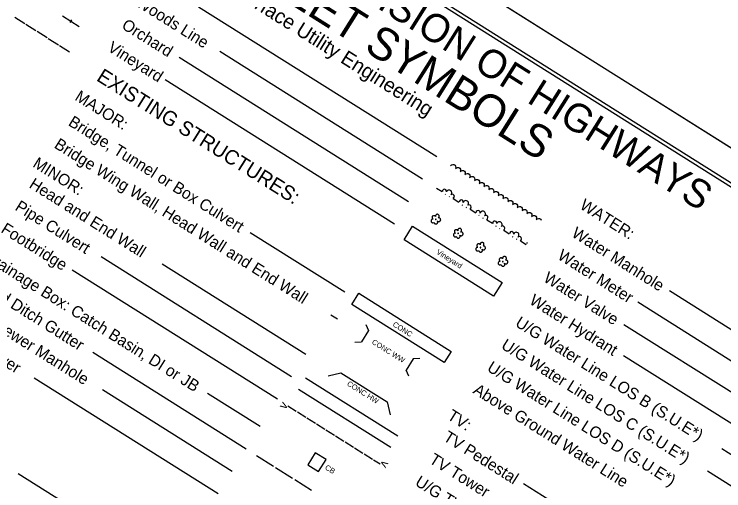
# Model space of a CAD drawing. Extents: x 2337092 to 2349158, y 800756 to 811724.
# Drawn here: x 2344308 to 2347526, y 805793 to 807955 of the extents above; entities that cross this region are included whole.
import ezdxf

# ---------------------------------------------------------------- set-up
doc = ezdxf.new("R2010")
doc.units = 0
for name, color, linetype in [('Sheet Cutting Line CELL', 7, 'Continuous'), ('Sheet Plot Border Inside CELL', 7, 'Continuous'), ('Sheet Plot Border Outside CELL', 7, 'Continuous'), ('Sheet Symbology CELL', 7, 'Continuous')]:
    doc.layers.add(name, color=color, linetype=linetype)

msp = doc.modelspace()

# ---------------------------------------------------------------- linework, layer by layer
at = {"layer": 'Sheet Cutting Line CELL'}
msp.add_line((2349158.5, 806341.3), (2340607.3, 811723.5), dxfattribs=at)
at = {"layer": 'Sheet Plot Border Inside CELL'}
msp.add_lwpolyline([(2337229.4, 806210.3), (2345691.7, 800884), (2349063.9, 806241.7), (2340601.5, 811568)], close=True, dxfattribs=at)
at = {"layer": 'Sheet Plot Border Outside CELL'}
msp.add_lwpolyline([(2337091.6, 806137.8), (2345642.8, 800755.6), (2349158.5, 806341.3), (2340607.3, 811723.5)], close=True, dxfattribs=at)
at = {"layer": 'Sheet Symbology CELL'}
for p, q in [((2346224.2, 807308.1), (2345144.1, 807987.8)), ((2344309.8, 807941.7), (2344355.5, 807912.9)), ((2344526, 807947.4), (2344602.2, 807899.4)), ((2344360.6, 807909.7), (2344406.3, 807881)), ((2344568.1, 807929.7), (2344560.1, 807917)), ((2344411.3, 807877.8), (2344457, 807849)), ((2344462.1, 807845.8), (2344507.8, 807817)), ((2344512.9, 807813.8), (2344558.6, 807785.1)), ((2346160.2, 807206.5), (2345240.5, 807785.4)), ((2346096.1, 807104.1), (2345055.5, 807759.1)), ((2346032.2, 807002.6), (2344991.6, 807657.5)), ((2346287.1, 807268.5), (2346291.6, 807272.3)), ((2346291.6, 807272.3), (2346296.8, 807273.7)), ((2346296.8, 807273.7), (2346302.3, 807273.4)), ((2346302.3, 807273.4), (2346307.1, 807270.4)), ((2346307.1, 807270.4), (2346309.6, 807265.3)), ((2346310.3, 807260.3), (2346308.6, 807255.3)), ((2346308.7, 807254.9), (2346313.2, 807258.8)), ((2346309.6, 807265.3), (2346310.3, 807260.3)), ((2346313.2, 807258.8), (2346318.4, 807260.1)), ((2346318.4, 807260.1), (2346323.9, 807259.9)), ((2346323.9, 807259.9), (2346328.7, 807256.8)), ((2346328.7, 807256.8), (2346331.1, 807251.7)), ((2346331.9, 807246.7), (2346330.2, 807241.7)), ((2346330.2, 807241.3), (2346334.8, 807245.2)), ((2346331.1, 807251.7), (2346331.9, 807246.7)), ((2346334.8, 807245.2), (2346339.9, 807246.6)), ((2346339.9, 807246.6), (2346345.4, 807246.3)), ((2346345.4, 807246.3), (2346350.3, 807243.2)), ((2346350.3, 807243.2), (2346352.7, 807238.1)), ((2346353.4, 807233.1), (2346351.7, 807228.1)), ((2346351.8, 807227.7), (2346356.4, 807231.6)), ((2346352.7, 807238.1), (2346353.4, 807233.1)), ((2346356.4, 807231.6), (2346361.5, 807233)), ((2346361.5, 807233), (2346367, 807232.7)), ((2346367, 807232.7), (2346371.8, 807229.7)), ((2346371.8, 807229.7), (2346374.3, 807224.6)), ((2346374.3, 807224.6), (2346375, 807219.5)), ((2346375, 807219.5), (2346373.3, 807214.6)), ((2346373.4, 807214.1), (2346378, 807218)), ((2346378, 807218), (2346383.1, 807219.4)), ((2346383.1, 807219.4), (2346388.6, 807219.1)), ((2346388.6, 807219.1), (2346393.4, 807216.1)), ((2346393.4, 807216.1), (2346395.9, 807211)), ((2346396.6, 807205.9), (2346394.9, 807201)), ((2346395, 807200.6), (2346399.6, 807204.4)), ((2346395.9, 807211), (2346396.6, 807205.9)), ((2346399.6, 807204.4), (2346404.7, 807205.8)), ((2346404.7, 807205.8), (2346410.2, 807205.5)), ((2346410.2, 807205.5), (2346415, 807202.5)), ((2346415, 807202.5), (2346417.5, 807197.4)), ((2346418.2, 807192.3), (2346416.5, 807187.4)), ((2346417.5, 807197.4), (2346418.2, 807192.3)), ((2346421.1, 807190.8), (2346426.3, 807192.2)), ((2346426.3, 807192.2), (2346431.8, 807191.9)), ((2346223.2, 807166.9), (2346248.6, 807150.9)), ((2346416.6, 807187), (2346421.1, 807190.8)), ((2346431.8, 807191.9), (2346436.6, 807188.9)), ((2346436.6, 807188.9), (2346439, 807183.8)), ((2346439.8, 807178.8), (2346438.1, 807173.8)), ((2346438.2, 807173.4), (2346442.7, 807177.3)), ((2346439, 807183.8), (2346439.8, 807178.8)), ((2346442.7, 807177.3), (2346447.8, 807178.6)), ((2346447.8, 807178.6), (2346453.3, 807178.4)), ((2346453.3, 807178.4), (2346458.2, 807175.3)), ((2346458.2, 807175.3), (2346460.6, 807170.2)), ((2346461.3, 807165.2), (2346459.6, 807160.2)), ((2346459.7, 807159.8), (2346464.3, 807163.7)), ((2346460.6, 807170.2), (2346461.3, 807165.2)), ((2346464.3, 807163.7), (2346469.4, 807165.1)), ((2346469.4, 807165.1), (2346474.9, 807164.8)), ((2346474.9, 807164.8), (2346479.7, 807161.7)), ((2346479.7, 807161.7), (2346482.2, 807156.6)), ((2346261.9, 807139), (2346264.5, 807137.4)), ((2346482.9, 807151.6), (2346481.2, 807146.6)), ((2346481.3, 807146.2), (2346485.9, 807150.1)), ((2346482.2, 807156.6), (2346482.9, 807151.6)), ((2346485.9, 807150.1), (2346491, 807151.5)), ((2346491, 807151.5), (2346496.5, 807151.2)), ((2346496.5, 807151.2), (2346501.3, 807148.2)), ((2346501.3, 807148.2), (2346503.8, 807143.1)), ((2346504.5, 807138), (2346502.8, 807133.1)), ((2346502.9, 807132.6), (2346507.5, 807136.5)), ((2346503.8, 807143.1), (2346504.5, 807138)), ((2346507.5, 807136.5), (2346512.6, 807137.9)), ((2346512.6, 807137.9), (2346518.1, 807137.6)), ((2346518.1, 807137.6), (2346522.9, 807134.6)), ((2346522.9, 807134.6), (2346525.4, 807129.5)), ((2346525.4, 807129.5), (2346526.1, 807124.4)), ((2346279.7, 807127.8), (2346282.2, 807126.2)), ((2346299.3, 807119), (2346324.7, 807103)), ((2346526.1, 807124.4), (2346524.4, 807119.5)), ((2346524.5, 807119.1), (2346529, 807122.9)), ((2346529, 807122.9), (2346534.2, 807124.3)), ((2346534.2, 807124.3), (2346539.7, 807124)), ((2346539.7, 807124), (2346544.5, 807121)), ((2346544.5, 807121), (2346547, 807115.9)), ((2346547.7, 807110.8), (2346546, 807105.9)), ((2346546.1, 807105.5), (2346550.6, 807109.3)), ((2346547, 807115.9), (2346547.7, 807110.8)), ((2346550.6, 807109.3), (2346555.7, 807110.7)), ((2346555.7, 807110.7), (2346561.2, 807110.4)), ((2346561.2, 807110.4), (2346566.1, 807107.4)), ((2346566.1, 807107.4), (2346568.5, 807102.3)), ((2346569.2, 807097.3), (2346567.5, 807092.3)), ((2346567.6, 807091.9), (2346572.2, 807095.8)), ((2346568.5, 807102.3), (2346569.2, 807097.3)), ((2346572.2, 807095.8), (2346577.3, 807097.1)), ((2346577.3, 807097.1), (2346582.8, 807096.9)), ((2346582.8, 807096.9), (2346587.6, 807093.8)), ((2346338.1, 807091), (2346340.6, 807089.4)), ((2346355.9, 807079.8), (2346358.4, 807078.2)), ((2346375.5, 807071), (2346400.9, 807055)), ((2346587.6, 807093.8), (2346590.1, 807088.7)), ((2346590.8, 807083.7), (2346589.1, 807078.7)), ((2346589.2, 807078.3), (2346593.8, 807082.2)), ((2346590.1, 807088.7), (2346590.8, 807083.7)), ((2346593.8, 807082.2), (2346598.9, 807083.6)), ((2346598.9, 807083.6), (2346604.4, 807083.3)), ((2346604.4, 807083.3), (2346609.2, 807080.2)), ((2346609.2, 807080.2), (2346611.7, 807075.1)), ((2346612.4, 807070.1), (2346610.7, 807065.1)), ((2346610.8, 807064.7), (2346615.4, 807068.6)), ((2346611.7, 807075.1), (2346612.4, 807070.1)), ((2346615.4, 807068.6), (2346620.5, 807070)), ((2346620.5, 807070), (2346626, 807069.7)), ((2346626, 807069.7), (2346630.8, 807066.7)), ((2346630.8, 807066.7), (2346633.3, 807061.6)), ((2346414.3, 807043.1), (2346416.8, 807041.5)), ((2346432, 807031.9), (2346434.6, 807030.3)), ((2346634, 807056.5), (2346632.3, 807051.6)), ((2346632.4, 807051.1), (2346636.9, 807055)), ((2346633.3, 807061.6), (2346634, 807056.5)), ((2346636.9, 807055), (2346642.1, 807056.4)), ((2346642.1, 807056.4), (2346647.6, 807056.1)), ((2346647.6, 807056.1), (2346652.4, 807053.1)), ((2346652.4, 807053.1), (2346654.9, 807048)), ((2346655.6, 807042.9), (2346653.9, 807038)), ((2346654, 807037.6), (2346658.5, 807041.4)), ((2346654.9, 807048), (2346655.6, 807042.9)), ((2346658.5, 807041.4), (2346663.6, 807042.8)), ((2346663.6, 807042.8), (2346669.1, 807042.5)), ((2346669.1, 807042.5), (2346674, 807039.5)), ((2346674, 807039.5), (2346676.4, 807034.4)), ((2346676.4, 807034.4), (2346677.2, 807029.3)), ((2346451.7, 807023.1), (2346477.1, 807007.1)), ((2346677.2, 807029.3), (2346675.5, 807024.4)), ((2346675.5, 807024), (2346680.1, 807027.8)), ((2346680.1, 807027.8), (2346685.2, 807029.2)), ((2346685.2, 807029.2), (2346690.7, 807028.9)), ((2346690.7, 807028.9), (2346695.6, 807025.9)), ((2346695.6, 807025.9), (2346698, 807020.8)), ((2346698, 807020.8), (2346698.1, 807020.4)), ((2346490.4, 806995.1), (2346493, 806993.5)), ((2346508.2, 806984), (2346510.8, 806982.4)), ((2346527.8, 806975.1), (2346553.2, 806959.2)), ((2345807.3, 806693.9), (2345378.6, 806963.7)), ((2346566.6, 806947.2), (2346569.1, 806945.6)), ((2346584.4, 806936), (2346586.9, 806934.4)), ((2346604, 806927.2), (2346629.4, 806911.2)), ((2345565.8, 806310.1), (2344701.6, 806854.1)), ((2345629.7, 806411.7), (2344978.2, 806821.7)), ((2345501.9, 806208.6), (2344570.2, 806795)), ((2348104.2, 806180.9), (2347279.6, 806699.9)), ((2348040.3, 806079.3), (2347136.2, 806648.4)), ((2345743.4, 806592.3), (2345773.8, 806573.2)), ((2345914.5, 806520.1), (2345882.5, 806469.3)), ((2345902.8, 806547.7), (2345914.5, 806520.1)), ((2347976.4, 805977.8), (2347072.3, 806546.8)), ((2345852.6, 806467.8), (2345882.5, 806469.3)), ((2345359.9, 805983), (2344664.5, 806420.7)), ((2346117.6, 806392.2), (2346085.7, 806341.4)), ((2346147.6, 806393.6), (2346117.6, 806392.2)), ((2347912.5, 805876.2), (2347070.6, 806406.1)), ((2345731.1, 806315.4), (2345789.7, 806328.7)), ((2345789.7, 806328.7), (2345999.1, 806196.9)), ((2346097.3, 806313.8), (2346085.7, 806341.4)), ((2345232, 805779.8), (2344398.2, 806304.6)), ((2345629, 806305.8), (2346047.9, 806042.1)), ((2345296, 805881.4), (2344708.6, 806251.1)), ((2345423.8, 806084.5), (2345184.1, 806235.4)), ((2345597, 806255), (2346016, 805991.3)), ((2345999.1, 806196.9), (2346012.4, 806138.4)), ((2345549.1, 806178.8), (2345587.2, 806154.9)), ((2345592.3, 806151.7), (2345630.3, 806127.7)), ((2345635.4, 806124.5), (2345673.5, 806100.5)), ((2345678.6, 806097.3), (2345716.7, 806073.4)), ((2345721.7, 806070.2), (2345759.8, 806046.2)), ((2345764.9, 806043), (2345803, 806019)), ((2345808.1, 806015.8), (2345846.2, 805991.9)), ((2345851.2, 805988.7), (2345889.3, 805964.7)), ((2347848.5, 805774.7), (2347516.5, 805983.6)), ((2345407.1, 805953.2), (2345483.3, 805905.3)), ((2345894.4, 805961.5), (2345932.5, 805937.5)), ((2345937.6, 805934.4), (2345968, 805915.2)), ((2345493.4, 805898.9), (2345569.6, 805851)), ((2347784.6, 805673.1), (2347452.6, 805882.1)), ((2345030.2, 805427.7), (2344325.9, 805871)), ((2345579.7, 805844.6), (2345655.9, 805796.6)), ((2347522, 805255.9), (2346618, 805824.9))]:
    msp.add_line(p, q, dxfattribs=at)
for points in [[(2348992.3, 806268.7), (2341375.4, 811062.8), (2338022.8, 805736.2), (2345639.6, 800942.1)], [(2345639.1, 805911.4), (2345687.9, 805880.6), (2345721.9, 805934.7), (2345673.1, 805965.4)]]:
    msp.add_lwpolyline(points, close=True, dxfattribs=at)
for points in [[(2346230.9, 807031.7), (2346232.6, 807032.7), (2346233.8, 807034.1), (2346234.6, 807035.8), (2346235.3, 807037.5), (2346235.3, 807039.2), (2346235.3, 807041), (2346234.7, 807042.8), (2346233.9, 807044.3), (2346232.5, 807046), (2346231.2, 807046.8), (2346229.5, 807047.5), (2346227.7, 807047.9), (2346225.9, 807047.9), (2346224, 807047.7), (2346222.3, 807046.7), (2346221, 807045.7), (2346219.8, 807044.4), (2346218.8, 807042.8), (2346218.1, 807041.2), (2346218.1, 807039.4), (2346218.1, 807037.3), (2346217.3, 807038.8), (2346216, 807040), (2346214.4, 807041), (2346212.8, 807041.3), (2346211.3, 807041.6), (2346209.4, 807041.4), (2346207.7, 807041), (2346206.1, 807040.2), (2346205.1, 807039.1), (2346203.7, 807037.5), (2346203.2, 807036), (2346202.9, 807034.4), (2346203.1, 807032.5), (2346203.2, 807031), (2346204, 807029.5), (2346205, 807027.8), (2346206.2, 807026.7), (2346207.7, 807025.7), (2346206.1, 807026), (2346204.2, 807025.8), (2346202.8, 807025.3), (2346201.3, 807024.1), (2346199.8, 807022.9), (2346199, 807021.6), (2346198.3, 807019.9), (2346198.3, 807018.2), (2346198.3, 807016.4), (2346198.6, 807014.8), (2346199.4, 807013.2), (2346200.4, 807011.9), (2346201.9, 807010.9), (2346203.4, 807010), (2346204.9, 807009.4), (2346206.8, 807009.7), (2346208.5, 807009.6), (2346211.2, 807011.1)], [(2346211.2, 807011.1), (2346213.2, 807007.4), (2346214.4, 807005.9), (2346215.7, 807004.7), (2346217.4, 807004), (2346219, 807003.7), (2346220.7, 807003.7), (2346222.7, 807003.9), (2346224.2, 807004.7), (2346225.5, 807005.7), (2346227, 807006.9), (2346227.7, 807008.5), (2346228.4, 807010.2), (2346228.3, 807012.4), (2346228.2, 807013.9), (2346227.4, 807015.4), (2346226.4, 807017.2), (2346227.7, 807015.9), (2346229.5, 807014.8), (2346231.1, 807014.5), (2346233.1, 807014.3), (2346234.9, 807014.3), (2346236.7, 807014.9), (2346238.4, 807016), (2346239.6, 807017.3), (2346240.8, 807018.7), (2346241.5, 807020.4), (2346242, 807022.2), (2346241.8, 807024.1), (2346241.3, 807026.2), (2346240.5, 807027.8), (2346239.3, 807029.2), (2346237.9, 807030.4), (2346236.4, 807031.4), (2346234.6, 807031.9), (2346232.8, 807031.9), (2346230.9, 807031.7)], [(2346221, 807025.5), (2346220.2, 807026), (2346219.6, 807026.1), (2346218.9, 807026.1), (2346218.4, 807025.4), (2346218.1, 807024.9), (2346218.3, 807024), (2346219.1, 807023.5), (2346219.6, 807023.2), (2346220.4, 807023.4), (2346221.1, 807024), (2346221.2, 807024.7), (2346221, 807025.5)], [(2346114.3, 806993.4), (2346520.5, 806737.7), (2346482.2, 806676.8), (2346076, 806932.5), (2346114.3, 806993.4)], [(2346332.5, 806967.8), (2346334.2, 806968.8), (2346335.4, 806970.2), (2346336.1, 806971.8), (2346336.8, 806973.5), (2346336.9, 806975.3), (2346336.9, 806977), (2346336.3, 806978.8), (2346335.5, 806980.4), (2346334, 806982), (2346332.7, 806982.8), (2346331.1, 806983.5), (2346329.2, 806984), (2346327.5, 806984), (2346325.6, 806983.8), (2346323.8, 806982.8), (2346322.5, 806981.8), (2346321.3, 806980.4), (2346320.4, 806978.9), (2346319.7, 806977.2), (2346319.6, 806975.5), (2346319.7, 806973.3), (2346318.9, 806974.9), (2346317.5, 806976.1), (2346316, 806977.1), (2346314.4, 806977.4), (2346312.8, 806977.6), (2346310.9, 806977.4), (2346309.3, 806977.1), (2346307.7, 806976.3), (2346306.6, 806975.2), (2346305.3, 806973.5), (2346304.7, 806972.1), (2346304.4, 806970.5), (2346304.6, 806968.6), (2346304.8, 806967.1), (2346305.6, 806965.6), (2346306.6, 806963.8), (2346307.7, 806962.8), (2346309.2, 806961.8), (2346307.6, 806962.1), (2346305.7, 806961.9), (2346304.3, 806961.4), (2346302.9, 806960.2), (2346301.4, 806959), (2346300.6, 806957.7), (2346299.9, 806956), (2346299.9, 806954.3), (2346299.8, 806952.5), (2346300.2, 806950.8), (2346301, 806949.3), (2346301.9, 806948), (2346303.5, 806947), (2346305, 806946.1), (2346306.4, 806945.5), (2346308.3, 806945.7), (2346310.1, 806945.7), (2346312.8, 806947.2)], [(2346312.8, 806947.2), (2346314.7, 806943.5), (2346315.9, 806942), (2346317.3, 806940.8), (2346319, 806940.1), (2346320.6, 806939.8), (2346322.3, 806939.8), (2346324.2, 806940), (2346325.8, 806940.8), (2346327.1, 806941.7), (2346328.5, 806942.9), (2346329.3, 806944.6), (2346330, 806946.3), (2346329.9, 806948.5), (2346329.8, 806950), (2346329, 806951.5), (2346327.9, 806953.2), (2346329.3, 806952), (2346331.1, 806950.9), (2346332.7, 806950.6), (2346334.7, 806950.4), (2346336.4, 806950.4), (2346338.2, 806951), (2346340, 806952.1), (2346341.2, 806953.4), (2346342.4, 806954.8), (2346343.1, 806956.5), (2346343.5, 806958.3), (2346343.3, 806960.2), (2346342.9, 806962.3), (2346342.1, 806963.8), (2346340.9, 806965.3), (2346339.5, 806966.5), (2346338, 806967.5), (2346336.1, 806967.9), (2346334.4, 806968), (2346332.5, 806967.8)], [(2346322.6, 806961.6), (2346321.8, 806962.1), (2346321.1, 806962.1), (2346320.5, 806962.2), (2346320, 806961.4), (2346319.7, 806960.9), (2346319.9, 806960.1), (2346320.6, 806959.6), (2346321.1, 806959.3), (2346322, 806959.5), (2346322.7, 806960.1), (2346322.8, 806960.8), (2346322.6, 806961.6)], [(2346434, 806903.8), (2346435.8, 806904.9), (2346437, 806906.2), (2346437.7, 806907.9), (2346438.4, 806909.6), (2346438.4, 806911.4), (2346438.4, 806913.1), (2346437.8, 806914.9), (2346437, 806916.5), (2346435.6, 806918.1), (2346434.3, 806918.9), (2346432.6, 806919.6), (2346430.8, 806920.1), (2346429, 806920.1), (2346427.1, 806919.9), (2346425.4, 806918.8), (2346424.1, 806917.9), (2346422.9, 806916.5), (2346421.9, 806915), (2346421.2, 806913.3), (2346421.2, 806911.6), (2346421.2, 806909.4), (2346420.4, 806911), (2346419.1, 806912.2), (2346417.6, 806913.1), (2346416, 806913.4), (2346414.4, 806913.7), (2346412.5, 806913.5), (2346410.8, 806913.1), (2346409.3, 806912.3), (2346408.2, 806911.2), (2346406.8, 806909.6), (2346406.3, 806908.2), (2346406, 806906.6), (2346406.2, 806904.7), (2346406.3, 806903.2), (2346407.1, 806901.6), (2346408.2, 806899.9), (2346409.3, 806898.9), (2346410.8, 806897.9), (2346409.2, 806898.2), (2346407.3, 806898), (2346405.9, 806897.4), (2346404.4, 806896.2), (2346403, 806895), (2346402.2, 806893.8), (2346401.5, 806892.1), (2346401.4, 806890.3), (2346401.4, 806888.6), (2346401.8, 806886.9), (2346402.6, 806885.4), (2346403.5, 806884.1), (2346405, 806883.1), (2346406.5, 806882.1), (2346408, 806881.6), (2346409.9, 806881.8), (2346411.6, 806881.8), (2346414.3, 806883.3)], [(2346414.3, 806883.3), (2346416.3, 806879.6), (2346417.5, 806878.1), (2346418.8, 806876.9), (2346420.5, 806876.2), (2346422.1, 806875.9), (2346423.9, 806875.9), (2346425.8, 806876.1), (2346427.3, 806876.9), (2346428.6, 806877.8), (2346430.1, 806879), (2346430.8, 806880.7), (2346431.5, 806882.4), (2346431.5, 806884.5), (2346431.3, 806886), (2346430.5, 806887.6), (2346429.5, 806889.3), (2346430.9, 806888.1), (2346432.6, 806887), (2346434.2, 806886.7), (2346436.2, 806886.5), (2346438, 806886.5), (2346439.8, 806887.1), (2346441.5, 806888.1), (2346442.7, 806889.5), (2346443.9, 806890.9), (2346444.6, 806892.5), (2346445.1, 806894.4), (2346444.9, 806896.3), (2346444.4, 806898.4), (2346443.6, 806899.9), (2346442.4, 806901.4), (2346441.1, 806902.6), (2346439.5, 806903.6), (2346437.7, 806904), (2346435.9, 806904.1), (2346434, 806903.8)], [(2346424.1, 806897.7), (2346423.4, 806898.1), (2346422.7, 806898.2), (2346422, 806898.3), (2346421.5, 806897.5), (2346421.2, 806897), (2346421.4, 806896.2), (2346422.2, 806895.7), (2346422.7, 806895.4), (2346423.5, 806895.6), (2346424.2, 806896.2), (2346424.3, 806896.8), (2346424.1, 806897.7)], [(2346535.6, 806839.9), (2346537.3, 806841), (2346538.5, 806842.3), (2346539.2, 806844), (2346539.9, 806845.7), (2346540, 806847.4), (2346540, 806849.2), (2346539.4, 806851), (2346538.6, 806852.6), (2346537.1, 806854.2), (2346535.9, 806855), (2346534.2, 806855.7), (2346532.3, 806856.1), (2346530.6, 806856.2), (2346528.7, 806856), (2346527, 806854.9), (2346525.6, 806854), (2346524.4, 806852.6), (2346523.5, 806851.1), (2346522.8, 806849.4), (2346522.7, 806847.7), (2346522.8, 806845.5), (2346522, 806847), (2346520.6, 806848.3), (2346519.1, 806849.2), (2346517.5, 806849.5), (2346515.9, 806849.8), (2346514, 806849.6), (2346512.4, 806849.2), (2346510.8, 806848.4), (2346509.8, 806847.3), (2346508.4, 806845.7), (2346507.8, 806844.3), (2346507.5, 806842.7), (2346507.8, 806840.8), (2346507.9, 806839.3), (2346508.7, 806837.7), (2346509.7, 806836), (2346510.8, 806834.9), (2346512.4, 806834), (2346510.8, 806834.3), (2346508.9, 806834.1), (2346507.5, 806833.5), (2346506, 806832.3), (2346504.5, 806831.1), (2346503.7, 806829.8), (2346503, 806828.2), (2346503, 806826.4), (2346502.9, 806824.7), (2346503.3, 806823), (2346504.1, 806821.4), (2346505.1, 806820.1), (2346506.6, 806819.2), (2346508.1, 806818.2), (2346509.5, 806817.7), (2346511.4, 806817.9), (2346513.2, 806817.9), (2346515.9, 806819.3)], [(2346515.9, 806819.3), (2346517.8, 806815.6), (2346519, 806814.2), (2346520.4, 806813), (2346522.1, 806812.3), (2346523.7, 806812), (2346525.4, 806811.9), (2346527.3, 806812.1), (2346528.9, 806812.9), (2346530.2, 806813.9), (2346531.7, 806815.1), (2346532.4, 806816.8), (2346533.1, 806818.5), (2346533, 806820.6), (2346532.9, 806822.1), (2346532.1, 806823.7), (2346531.1, 806825.4), (2346532.4, 806824.2), (2346534.2, 806823.1), (2346535.8, 806822.8), (2346537.8, 806822.6), (2346539.5, 806822.5), (2346541.4, 806823.2), (2346543.1, 806824.2), (2346544.3, 806825.6), (2346545.5, 806826.9), (2346546.2, 806828.6), (2346546.7, 806830.5), (2346546.4, 806832.4), (2346546, 806834.4), (2346545.2, 806836), (2346544, 806837.5), (2346542.6, 806838.7), (2346541.1, 806839.6), (2346539.2, 806840.1), (2346537.5, 806840.1), (2346535.6, 806839.9)], [(2346525.7, 806833.7), (2346524.9, 806834.2), (2346524.2, 806834.3), (2346523.6, 806834.4), (2346523.1, 806833.6), (2346522.8, 806833.1), (2346523, 806832.3), (2346523.7, 806831.8), (2346524.2, 806831.5), (2346525.1, 806831.6), (2346525.8, 806832.3), (2346525.9, 806832.9), (2346525.7, 806833.7)], [(2345870.5, 806689.5), (2346289.5, 806425.9), (2346257.5, 806375.1), (2345838.6, 806638.8), (2345870.5, 806689.5)]]:
    msp.add_lwpolyline(points, dxfattribs=at)
for centre, radius, start, end in [((2346259.2, 807151.5), 9.49, 346.2484, 187.045), ((2346280.1, 807145.3), 12.4, 313.7772, 161.8497), ((2346294.7, 807129.1), 9.49, 288.5819, 129.3785), ((2346335.3, 807103.5), 9.49, 346.2484, 187.045), ((2346356.3, 807097.4), 12.4, 313.7772, 161.8497), ((2346370.9, 807081.1), 9.49, 288.5819, 129.3785), ((2346411.5, 807055.6), 9.49, 346.2484, 187.045), ((2346432.5, 807049.5), 12.4, 313.7772, 161.8497), ((2346447, 807033.2), 9.49, 288.5819, 129.3785), ((2346487.7, 807007.6), 9.49, 346.2484, 187.045), ((2346508.6, 807001.5), 12.4, 313.7772, 161.8497), ((2346523.2, 806985.3), 9.49, 288.5819, 129.3785), ((2346563.8, 806959.7), 9.49, 346.2484, 187.045), ((2346584.8, 806953.6), 12.4, 313.7772, 161.8497), ((2346599.4, 806937.3), 9.49, 288.5819, 129.3785), ((2346640, 806911.8), 9.49, 124.0645, 171.5624)]:
    msp.add_arc(centre, radius, start, end, dxfattribs=at)

# ---------------------------------------------------------------- texts
for s, height, rotation, p in [('STATE OF NORTH CAROLINA, DIVISION OF HIGHWAYS', 128.514, 327.8134, (2343573.9, 809480.8)), ('CONVENTIONAL  PLAN SHEET SYMBOLS', 146.882, 327.8134, (2343404.1, 809356.8)), ('*S.U.E. = Subsurface Utility Engineering', 66, 327.8134, (2344850.9, 808325.9)), ('Woods Line', 52.5, 327.8134, (2344855.2, 807995.9)), ('Orchard', 52.5, 327.8134, (2344791, 807893.5)), ('Vineyard', 52.5, 327.8134, (2344727.1, 807791.9)), ('EXISTING STRUCTURES:', 66, 327.8134, (2344676.7, 807656.8)), ('MAJOR:', 52.5, 327.8134, (2344578.7, 807568.8)), ('Bridge, Tunnel or Box Culvert', 52.5, 327.8134, (2344548.9, 807453.7)), ('Bridge Wing Wall, Head Wall and End Wall', 52.5, 327.8134, (2344485, 807352.1)), ('MINOR:', 52.5, 327.8134, (2344387.8, 807265.7)), ('Head and End Wall', 52.5, 327.8134, (2344371.3, 807171.5)), ('Pipe Culvert', 52.5, 327.8134, (2344307.4, 807070)), ('WATER:', 52.5, 327.8134, (2346869, 807076.5)), ('Footbridge', 52.5, 327.8134, (2344243.5, 806968.4)), ('Water Manhole', 52.5, 327.8134, (2346831.9, 806949.5)), ('Drainage Box: Catch Basin, DI or JB', 52.5, 327.8134, (2344165.5, 806844.4)), ('Vineyard', 24, 327.8135, (2346219.9, 806870.2)), ('Water Meter', 52.5, 327.8134, (2346768, 806848)), ('Paved Ditch Gutter', 52.5, 327.8134, (2344101.5, 806742.7)), ('Water Valve', 52.5, 327.8134, (2346704.1, 806746.4)), ('Storm Sewer Manhole', 52.5, 327.8134, (2344037.6, 806641.2)), ('Water Hydrant', 52.5, 327.8134, (2346640.2, 806644.9)), ('U/G Water Line LOS B (S.U.E*)', 52.5, 327.8134, (2346576.2, 806543.3)), ('Storm Sewer', 52.5, 327.8134, (2343973.7, 806539.6)), ('CONC', 24, 327.8134, (2346021.9, 806542.1)), ('CONC WW', 24, 327.8135, (2345927, 806462.5)), ('U/G Water Line LOS C (S.U.E*)', 52.5, 327.8134, (2346512.3, 806441.7)), ('U/G Water Line LOS D (S.U.E*)', 52.5, 327.8134, (2346448.4, 806340.2)), ('CONC HW', 24, 327.8134, (2345814.3, 806273.1)), ('Above Ground Water Line', 52.5, 327.8134, (2346384.5, 806238.6)), ('v', 39.6, 57.5726, (2345537.1, 806159.9)), ('TV:', 52.5, 327.8134, (2346267.8, 806121.5)), ('TV Pedestal', 52.5, 327.8134, (2346249.7, 806024.5)), ('TV Tower', 52.5, 327.8134, (2346185.8, 805923)), ('CB', 24, 327.8134, (2345714.5, 805893.2)), ('v', 39.6, 238.0543, (2345979.9, 805934.2)), ('U/G TV Cable Hand Hole', 52.5, 327.8134, (2346121.9, 805821.4))]:
    msp.add_text(s, height=height, rotation=rotation, dxfattribs=at).set_placement(p)

doc.saveas('drawing.dxf')
